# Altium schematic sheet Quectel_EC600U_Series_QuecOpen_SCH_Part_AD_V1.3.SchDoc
size A2
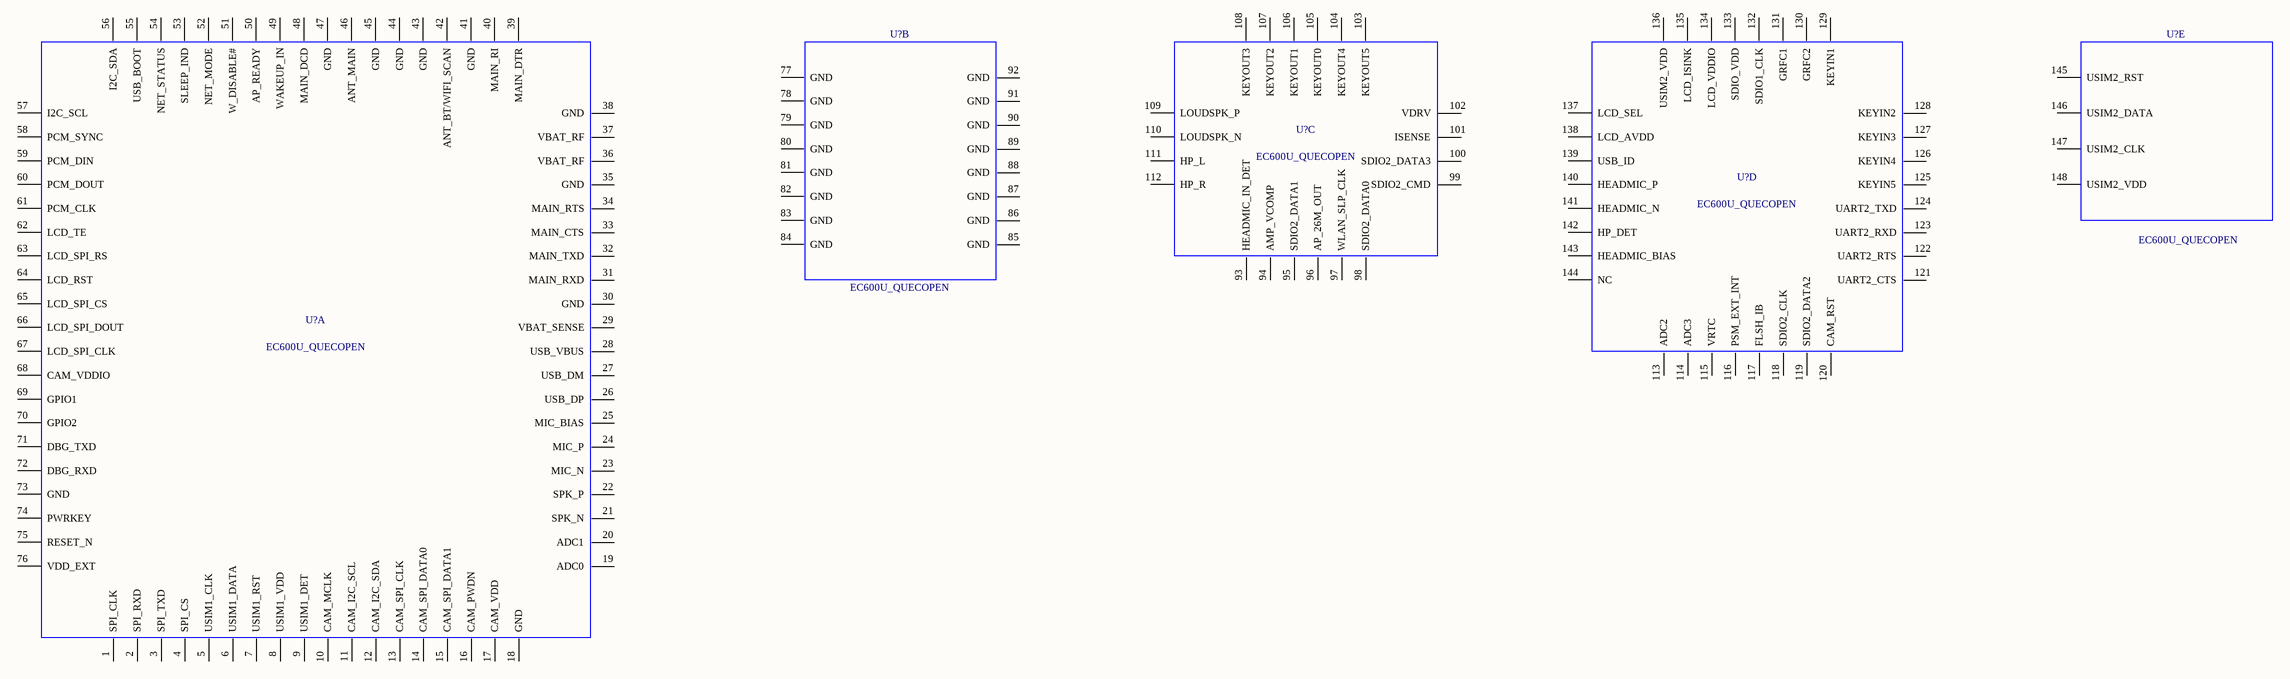
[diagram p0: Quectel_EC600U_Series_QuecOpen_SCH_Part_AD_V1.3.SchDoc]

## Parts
(Parts that share a designator on the sheet are numbered #1, #2 ... from top to bottom, then left to right.)
U?#1  EC600U_QUECOPEN  (part E of 5)
U?#2  EC600U_QUECOPEN  (part C of 5)
U?#3  EC600U_QUECOPEN  (part B of 5)
U?#4  EC600U_QUECOPEN  (part D of 5)
U?#5  EC600U_QUECOPEN  (part A of 5)

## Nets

Not connected (* = marked no-connect by the designer): U?#1 145(USIM2_RST) 146(USIM2_DATA) 147(USIM2_CLK) 148(USIM2_VDD); U?#2 93(HEADMIC_IN_DET) 94(AMP_VCOMP) 95(SDIO2_DATA1) 96(AP_26M_OUT) 97(WLAN_SLP_CLK) 98(SDIO2_DATA0) 99(SDIO2_CMD) 100(SDIO2_DATA3) 101(ISENSE) 102(VDRV) 103(KEYOUT5) 104(KEYOUT4) 105(KEYOUT0) 106(KEYOUT1) 107(KEYOUT2) 108(KEYOUT3) 109(LOUDSPK_P) 110(LOUDSPK_N) 111(HP_L) 112(HP_R); U?#3 77(GND) 78(GND) 79(GND) 80(GND) 81(GND) 82(GND) 83(GND) 84(GND) 85(GND) 86(GND) 87(GND) 88(GND) 89(GND) 90(GND) 91(GND) 92(GND); U?#4 113(ADC2) 114(ADC3) 115(VRTC) 116(PSM_EXT_INT) 117(FLSH_IB) 118(SDIO2_CLK) 119(SDIO2_DATA2) 120(CAM_RST) 121(UART2_CTS) 122(UART2_RTS) 123(UART2_RXD) 124(UART2_TXD) 125(KEYIN5) 126(KEYIN4) 127(KEYIN3) 128(KEYIN2) 129(KEYIN1) 130(GRFC2) 131(GRFC1) 132(SDIO1_CLK) 133(SDIO_VDD) 134(LCD_VDDIO) 135(LCD_ISINK) 136(USIM2_VDD) 137(LCD_SEL) 138(LCD_AVDD) 139(USB_ID) 140(HEADMIC_P) 141(HEADMIC_N) 142(HP_DET) 143(HEADMIC_BIAS) 144(NC); U?#5 1(SPI_CLK) 2(SPI_RXD) 3(SPI_TXD) 4(SPI_CS) 5(USIM1_CLK) 6(USIM1_DATA) 7(USIM1_RST) 8(USIM1_VDD) 9(USIM1_DET) 10(CAM_MCLK) 11(CAM_I2C_SCL) 12(CAM_I2C_SDA) 13(CAM_SPI_CLK) 14(CAM_SPI_DATA0) 15(CAM_SPI_DATA1) 16(CAM_PWDN) 17(CAM_VDD) 18(GND) 19(ADC0) 20(ADC1) 21(SPK_N) 22(SPK_P) 23(MIC_N) 24(MIC_P) 25(MIC_BIAS) 26(USB_DP) 27(USB_DM) 28(USB_VBUS) 29(VBAT_SENSE) 30(GND) 31(MAIN_RXD) 32(MAIN_TXD) 33(MAIN_CTS) 34(MAIN_RTS) 35(GND) 36(VBAT_RF) 37(VBAT_RF) 38(GND) 39(MAIN_DTR) 40(MAIN_RI) 41(GND) 42(ANT_BT/WIFI_SCAN) 43(GND) 44(GND) 45(GND) 46(ANT_MAIN) 47(GND) 48(MAIN_DCD) 49(WAKEUP_IN) 50(AP_READY) 51(W_DISABLE#) 52(NET_MODE) 53(SLEEP_IND) 54(NET_STATUS) 55(USB_BOOT) 56(I2C_SDA) 57(I2C_SCL) 58(PCM_SYNC) 59(PCM_DIN) 60(PCM_DOUT) 61(PCM_CLK) 62(LCD_TE) 63(LCD_SPI_RS) 64(LCD_RST) 65(LCD_SPI_CS) 66(LCD_SPI_DOUT) 67(LCD_SPI_CLK) 68(CAM_VDDIO) 69(GPIO1) 70(GPIO2) 71(DBG_TXD) 72(DBG_RXD) 73(GND) 74(PWRKEY) 75(RESET_N) 76(VDD_EXT)

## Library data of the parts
U?#1-U?#5 = EC600U_QUECOPEN: EC600U_QuecOpen Module LCC76PIN LGA72PIN H2.4mm RO; Manufacturer: Quectel; Geometry.Height: 2.4mm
